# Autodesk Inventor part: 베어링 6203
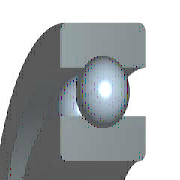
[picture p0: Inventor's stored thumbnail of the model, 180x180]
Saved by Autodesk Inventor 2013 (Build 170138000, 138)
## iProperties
IsCustomPart: 0
Company: 한국ATC센터
Created: 2015-11
Part Number: 베어링 6203
Material: 강철, 연강
Description: 깊은 그루브 볼 베어링
Document SubType Name: Modeling
Standard: KS B 2023
Designer: mdu
Standards Organization: KS
Language: ko-KR
Size Designation: 6203 - 17 x 40 x 12
Categories: <MemberInstance><Categories><Category DisplayName="샤프트 부품" InternalName="7f7aeb1f-a693-4053-b835-cee3144e0d98" Mnemonic="SHFT"><Category DisplayName="베어링" Inter
Density: 1 g/cm^3
Author: mdu
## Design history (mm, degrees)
sketch "스케치" dims "d0" = 5.98 (= -0.26 x WD + 0.26 x BD)
  geometry: L1 (3.01, 14.25)-(8.99, 14.25); L2 (6, 14.25)-(6, 11.26); L3 (6, 14.25)-(6, 17.24); L4 (3.778, 12.249)-(0, 12.249); L5 (0, 8.5)-(12, 8.5); L6 (3.778, 16.251)-(0, 16.251); L7 (0, 20)-(12, 20); L8 (12, 8.5)-(12, 12.249); L9 (8.222, 12.249)-(12, 12.249); L10 (8.222, 16.251)-(12, 16.251); L11 (12, 20)-(12, 16.251); L12 (-1.4, 0)-(8.4, 0) reference; L13 (0, -0.3)-(0, 5.3) reference
  constraints: 22 end point, 4 point on line, 2 collinear, 2 perpendicular, 2 symmetric about line, 1 midpoint, 1 parallel, 14 other
  dimensions: "d9" = 17 diameter of L5 L12 (= WD); "d11" = 40 diameter of L7 L12 (= BD); "d12" = 12 distance between parallel lines of L8 L13 (= KB); "d13" = 24.498 diameter of L9 L12 (= 0.326 x BD + 0.674 x WD)
revolve "본체" stored, may be unused: angle "d6" = 90 deg
revolve "볼" stored, may be unused: angle "d7" = 90 deg
pattern_circular "IDS_ARRAYBALL[SIMPL:T]" dims angle "d3" = 360 deg
body "Solid1"
fillet "모깎기1" dims "d1" = 0.6 (= KRS)
other parameters: "WD" = 17 [user parameter; used in 5 equation terms], "BD" = 40 [user parameter; used in 5 equation terms], "KB" = 12 [user parameter; used in 1 equation term], "KRS" = 0.6 [user parameter; used in 1 equation term], "d4" = 0, "d5" = 0, "d8" = 0, "d14" = 0, "d15" = 0, "BBA" = 0 [user parameter], "BC0" = 4750000 [user parameter], "BC" = 9560000 [user parameter], "WR" = 8.5 (= 0.5 x WD) [user parameter]
